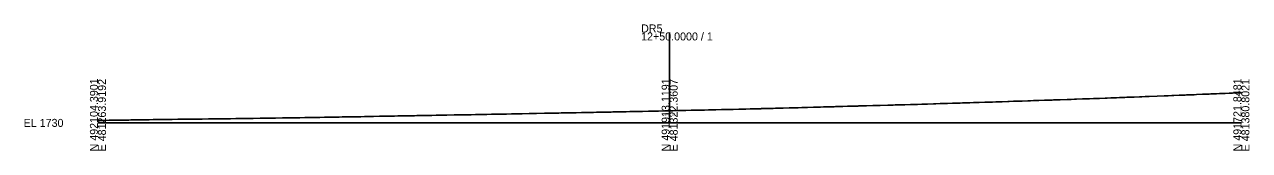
# Model space of a CAD drawing. Extents: x -26 to 403, y -10 to 2534.
# Drawn here: x -25.7 to 402.8, y 2490.3 to 2534.5 of the extents above; entities that cross this region are included whole.
import ezdxf

# ---------------------------------------------------------------- set-up
doc = ezdxf.new("R2010")
doc.units = 0
for name, color, linetype in [('Exist Cross Section Cell', 7, 'Continuous'), ('Exist XS Center Line Elevation Label', 7, 'Continuous'), ('Exist XS Ground Line', 7, 'Continuous'), ('Scratch_Level_5', 7, 'Continuous')]:
    doc.layers.add(name, color=color, linetype=linetype)

msp = doc.modelspace()

# ---------------------------------------------------------------- linework, layer by layer
at = {"layer": 'Exist Cross Section Cell'}
for p, q in [((200, 2500), (200, 2531.7)), ((0, 2500), (200, 2500)), ((200, 2500), (400, 2500))]:
    msp.add_line(p, q, dxfattribs=at)
at = {"layer": 'Exist XS Ground Line'}
msp.add_lwpolyline([(0, 2500.85), (0.97, 2500.87), (1.82, 2500.88), (2.29, 2500.88), (3.87, 2500.91), (4.94, 2500.93), (6.19, 2500.95), (7.26, 2500.96), (8.12, 2500.98), (9.65, 2501), (10.78, 2501.01), (11.56, 2501.03), (12.28, 2501.04), (13.59, 2501.05), (14.87, 2501.07), (15.84, 2501.09), (17.48, 2501.11), (17.92, 2501.12), (19.34, 2501.14), (20.08, 2501.15), (20.42, 2501.15), (22.53, 2501.18), (24.23, 2501.21), (25.34, 2501.22), (25.94, 2501.23), (27.95, 2501.26), (30.28, 2501.29), (31.04, 2501.29), (31.72, 2501.3), (33.18, 2501.32), (35.47, 2501.35), (35.94, 2501.35), (36.48, 2501.36), (38.69, 2501.39), (40.44, 2501.41), (41.01, 2501.42), (41.95, 2501.43), (43.64, 2501.44), (45.01, 2501.46), (46.35, 2501.47), (48.24, 2501.5), (48.86, 2501.51), (50.54, 2501.52), (51.47, 2501.54), (53.64, 2501.57), (54.26, 2501.58), (56.71, 2501.62), (57.94, 2501.64), (59.31, 2501.65), (59.98, 2501.66), (62.17, 2501.7), (64.54, 2501.74), (65.97, 2501.76), (67.16, 2501.78), (68, 2501.79), (69.78, 2501.81), (70.68, 2501.83), (72.38, 2501.86), (74, 2501.89), (75.02, 2501.9), (76.89, 2501.93), (77.6, 2501.94), (79.25, 2501.97), (80.22, 2501.98), (80.64, 2501.99), (82.85, 2502.02), (84.43, 2502.05), (85.45, 2502.07), (86, 2502.08), (88.09, 2502.11), (90.01, 2502.15), (90.68, 2502.16), (92, 2502.18), (93.3, 2502.21), (94.03, 2502.22), (95.92, 2502.26), (96.38, 2502.26), (98.52, 2502.3), (100.03, 2502.33), (101.15, 2502.35), (103.23, 2502.39), (103.74, 2502.4), (104.91, 2502.42), (106.02, 2502.44), (106.36, 2502.45), (106.99, 2502.46), (108.99, 2502.49), (110.78, 2502.53), (111.59, 2502.54), (113.47, 2502.57), (114.21, 2502.59), (114.53, 2502.59), (116.83, 2502.63), (118.29, 2502.66), (119.43, 2502.68), (120.06, 2502.69), (122.08, 2502.72), (124.66, 2502.77), (126.04, 2502.79), (127.29, 2502.82), (128.07, 2502.83), (129.91, 2502.86), (130.57, 2502.87), (132.04, 2502.9), (132.5, 2502.91), (134.06, 2502.93), (135.14, 2502.95), (136.08, 2502.97), (137.73, 2503), (139.09, 2503.02), (140.35, 2503.04), (142.08, 2503.08), (142.97, 2503.09), (144.65, 2503.13), (145.58, 2503.14), (147.68, 2503.18), (148.41, 2503.2), (150.82, 2503.25), (152.18, 2503.27), (153.42, 2503.29), (156.25, 2503.35), (158.66, 2503.4), (159.73, 2503.42), (161.26, 2503.45), (162.07, 2503.47), (164.1, 2503.5), (164.82, 2503.52), (166.51, 2503.55), (167.26, 2503.57), (169.1, 2503.6), (170.08, 2503.62), (171.72, 2503.65), (172.1, 2503.66), (173.37, 2503.69), (174.35, 2503.7), (174.78, 2503.71), (176.95, 2503.75), (178.09, 2503.78), (179.56, 2503.8), (180.11, 2503.82), (182.31, 2503.86), (184.8, 2503.91), (186.08, 2503.94), (187.4, 2503.96), (188.12, 2503.98), (190.13, 2504.02), (190.48, 2504.03), (192.64, 2504.07), (193.59, 2504.09), (195.25, 2504.13), (196.11, 2504.15), (198.14, 2504.2), (199.05, 2504.22), (200.15, 2504.24), (200.48, 2504.25), (201.1, 2504.26), (203.09, 2504.3), (204.88, 2504.35), (205.7, 2504.37), (207.56, 2504.41), (208.31, 2504.43), (210.15, 2504.46), (210.94, 2504.48), (212.17, 2504.51), (213.55, 2504.54), (216.14, 2504.6), (218.15, 2504.64), (218.77, 2504.66), (220.16, 2504.69), (221.4, 2504.72), (222.17, 2504.74), (224.18, 2504.79), (224.69, 2504.8), (226.62, 2504.85), (228.16, 2504.89), (229.23, 2504.91), (230.17, 2504.94), (231.85, 2504.98), (232.17, 2504.99), (233.25, 2505.01), (234.46, 2505.04), (236.19, 2505.09), (237.08, 2505.11), (238.76, 2505.15), (239.68, 2505.18), (241.78, 2505.24), (242.29, 2505.25), (244.18, 2505.3), (244.91, 2505.32), (246.19, 2505.36), (247.54, 2505.4), (248.2, 2505.41), (250.35, 2505.47), (252.76, 2505.54), (253.82, 2505.57), (255.38, 2505.61), (257.58, 2505.68), (257.98, 2505.69), (258.88, 2505.72), (260.2, 2505.75), (260.59, 2505.77), (262.21, 2505.81), (263.22, 2505.84), (264.22, 2505.87), (265.84, 2505.91), (266.22, 2505.92), (267.47, 2505.96), (268.45, 2505.98), (268.88, 2506), (271.06, 2506.06), (272.64, 2506.1), (273.67, 2506.13), (276.28, 2506.21), (278.22, 2506.26), (278.9, 2506.28), (280.23, 2506.32), (281.51, 2506.35), (282.23, 2506.37), (284.24, 2506.43), (284.6, 2506.44), (286.24, 2506.49), (286.75, 2506.5), (288.24, 2506.55), (289.36, 2506.58), (290.25, 2506.61), (292.25, 2506.66), (293.13, 2506.69), (294.59, 2506.74), (295.24, 2506.76), (297.2, 2506.82), (298.99, 2506.87), (299.81, 2506.9), (301.67, 2506.96), (302.42, 2506.98), (304.25, 2507.04), (305.04, 2507.06), (306.26, 2507.1), (307.66, 2507.14), (308.26, 2507.16), (310.27, 2507.22), (312.27, 2507.29), (312.89, 2507.31), (314.06, 2507.35), (315.5, 2507.4), (316.27, 2507.43), (318.27, 2507.49), (318.77, 2507.51), (320.28, 2507.56), (320.73, 2507.57), (321.58, 2507.6), (323.34, 2507.66), (325.35, 2507.72), (325.95, 2507.75), (326.27, 2507.76), (327.33, 2507.79), (328.58, 2507.83), (329.12, 2507.85), (331.18, 2507.92), (332.87, 2507.98), (333.8, 2508.02), (334.29, 2508.03), (335.89, 2508.09), (336.65, 2508.11), (339.03, 2508.2), (340.41, 2508.24), (341.64, 2508.28), (342.3, 2508.3), (344.45, 2508.38), (346.3, 2508.45), (346.87, 2508.47), (348.3, 2508.52), (349.48, 2508.57), (350.31, 2508.6), (352.31, 2508.68), (353.01, 2508.7), (354.31, 2508.75), (354.7, 2508.77), (356.32, 2508.83), (357.33, 2508.87), (359.23, 2508.94), (359.93, 2508.97), (361.52, 2509.03), (362.55, 2509.06), (364.32, 2509.13), (365.17, 2509.17), (366.32, 2509.21), (367.77, 2509.27), (370.5, 2509.38), (373.01, 2509.47), (374.33, 2509.52), (375.63, 2509.58), (376.34, 2509.6), (378.24, 2509.68), (378.68, 2509.7), (380.34, 2509.77), (380.85, 2509.79), (381.82, 2509.83), (383.46, 2509.89), (384.33, 2509.93), (386.34, 2510.01), (387.23, 2510.05), (388.35, 2510.1), (388.69, 2510.11), (389.33, 2510.14), (391.32, 2510.22), (392.35, 2510.26), (393.92, 2510.32), (394.36, 2510.33), (395.76, 2510.39), (396.53, 2510.42), (396.87, 2510.44), (399.13, 2510.53), (400, 2510.57)], dxfattribs=at)
at = {"layer": 'Scratch_Level_5'}
msp.add_lwpolyline([(0, 2500.85), (0.97, 2500.87), (1.82, 2500.88), (2.29, 2500.88), (3.87, 2500.91), (4.94, 2500.93), (6.19, 2500.95), (7.26, 2500.96), (8.12, 2500.98), (9.65, 2501), (10.78, 2501.01), (11.56, 2501.03), (12.28, 2501.04), (13.59, 2501.05), (14.87, 2501.07), (15.84, 2501.09), (17.48, 2501.11), (17.92, 2501.12), (19.34, 2501.14), (20.08, 2501.15), (20.42, 2501.15), (22.53, 2501.18), (24.23, 2501.21), (25.34, 2501.22), (25.94, 2501.23), (27.95, 2501.26), (30.28, 2501.29), (31.04, 2501.29), (31.72, 2501.3), (33.18, 2501.32), (35.47, 2501.35), (35.94, 2501.35), (36.48, 2501.36), (38.69, 2501.39), (40.44, 2501.41), (41.01, 2501.42), (41.95, 2501.43), (43.64, 2501.44), (45.01, 2501.46), (46.35, 2501.47), (48.24, 2501.5), (48.86, 2501.51), (50.54, 2501.52), (51.47, 2501.54), (53.64, 2501.57), (54.26, 2501.58), (56.71, 2501.62), (57.94, 2501.64), (59.31, 2501.65), (59.98, 2501.66), (62.17, 2501.7), (64.54, 2501.74), (65.97, 2501.76), (67.16, 2501.78), (68, 2501.79), (69.78, 2501.81), (70.68, 2501.83), (72.38, 2501.86), (74, 2501.89), (75.02, 2501.9), (76.89, 2501.93), (77.6, 2501.94), (79.25, 2501.97), (80.22, 2501.98), (80.64, 2501.99), (82.85, 2502.02), (84.43, 2502.05), (85.45, 2502.07), (86, 2502.08), (88.09, 2502.11), (90.01, 2502.15), (90.68, 2502.16), (92, 2502.18), (93.3, 2502.21), (94.03, 2502.22), (95.92, 2502.26), (96.38, 2502.26), (98.52, 2502.3), (100.03, 2502.33), (101.15, 2502.35), (103.23, 2502.39), (103.74, 2502.4), (104.91, 2502.42), (106.02, 2502.44), (106.36, 2502.45), (106.99, 2502.46), (108.99, 2502.49), (110.78, 2502.53), (111.59, 2502.54), (113.47, 2502.57), (114.21, 2502.59), (114.53, 2502.59), (116.83, 2502.63), (118.29, 2502.66), (119.43, 2502.68), (120.06, 2502.69), (122.08, 2502.72), (124.66, 2502.77), (126.04, 2502.79), (127.29, 2502.82), (128.07, 2502.83), (129.91, 2502.86), (130.57, 2502.87), (132.04, 2502.9), (132.5, 2502.91), (134.06, 2502.93), (135.14, 2502.95), (136.08, 2502.97), (137.73, 2503), (139.09, 2503.02), (140.35, 2503.04), (142.08, 2503.08), (142.97, 2503.09), (144.65, 2503.13), (145.58, 2503.14), (147.68, 2503.18), (148.41, 2503.2), (150.82, 2503.25), (152.18, 2503.27), (153.42, 2503.29), (156.25, 2503.35), (158.66, 2503.4), (159.73, 2503.42), (161.26, 2503.45), (162.07, 2503.47), (164.1, 2503.5), (164.82, 2503.52), (166.51, 2503.55), (167.26, 2503.57), (169.1, 2503.6), (170.08, 2503.62), (171.72, 2503.65), (172.1, 2503.66), (173.37, 2503.69), (174.35, 2503.7), (174.78, 2503.71), (176.95, 2503.75), (178.09, 2503.78), (179.56, 2503.8), (180.11, 2503.82), (182.31, 2503.86), (184.8, 2503.91), (186.08, 2503.94), (187.4, 2503.96), (188.12, 2503.98), (190.13, 2504.02), (190.48, 2504.03), (192.64, 2504.07), (193.59, 2504.09), (195.25, 2504.13), (196.11, 2504.15), (198.14, 2504.2), (199.05, 2504.22), (200.15, 2504.24), (200.48, 2504.25), (201.1, 2504.26), (203.09, 2504.3), (204.88, 2504.35), (205.7, 2504.37), (207.56, 2504.41), (208.31, 2504.43), (210.15, 2504.46), (210.94, 2504.48), (212.17, 2504.51), (213.55, 2504.54), (216.14, 2504.6), (218.15, 2504.64), (218.77, 2504.66), (220.16, 2504.69), (221.4, 2504.72), (222.17, 2504.74), (224.18, 2504.79), (224.69, 2504.8), (226.62, 2504.85), (228.16, 2504.89), (229.23, 2504.91), (230.17, 2504.94), (231.85, 2504.98), (232.17, 2504.99), (233.25, 2505.01), (234.46, 2505.04), (236.19, 2505.09), (237.08, 2505.11), (238.76, 2505.15), (239.68, 2505.18), (241.78, 2505.24), (242.29, 2505.25), (244.18, 2505.3), (244.91, 2505.32), (246.19, 2505.36), (247.54, 2505.4), (248.2, 2505.41), (250.35, 2505.47), (252.76, 2505.54), (253.82, 2505.57), (255.38, 2505.61), (257.58, 2505.68), (257.98, 2505.69), (258.88, 2505.72), (260.2, 2505.75), (260.59, 2505.77), (262.21, 2505.81), (263.22, 2505.84), (264.22, 2505.87), (265.84, 2505.91), (266.22, 2505.92), (267.47, 2505.96), (268.45, 2505.98), (268.88, 2506), (271.06, 2506.06), (272.64, 2506.1), (273.67, 2506.13), (276.28, 2506.21), (278.22, 2506.26), (278.9, 2506.28), (280.23, 2506.32), (281.51, 2506.35), (282.23, 2506.37), (284.24, 2506.43), (284.6, 2506.44), (286.24, 2506.49), (286.75, 2506.5), (288.24, 2506.55), (289.36, 2506.58), (290.25, 2506.61), (292.25, 2506.66), (293.13, 2506.69), (294.59, 2506.74), (295.24, 2506.76), (297.2, 2506.82), (298.99, 2506.87), (299.81, 2506.9), (301.67, 2506.96), (302.42, 2506.98), (304.25, 2507.04), (305.04, 2507.06), (306.26, 2507.1), (307.66, 2507.14), (308.26, 2507.16), (310.27, 2507.22), (312.27, 2507.29), (312.89, 2507.31), (314.06, 2507.35), (315.5, 2507.4), (316.27, 2507.43), (318.27, 2507.49), (318.77, 2507.51), (320.28, 2507.56), (320.73, 2507.57), (321.58, 2507.6), (323.34, 2507.66), (325.35, 2507.72), (325.95, 2507.75), (326.27, 2507.76), (327.33, 2507.79), (328.58, 2507.83), (329.12, 2507.85), (331.18, 2507.92), (332.87, 2507.98), (333.8, 2508.02), (334.29, 2508.03), (335.89, 2508.09), (336.65, 2508.11), (339.03, 2508.2), (340.41, 2508.24), (341.64, 2508.28), (342.3, 2508.3), (344.45, 2508.38), (346.3, 2508.45), (346.87, 2508.47), (348.3, 2508.52), (349.48, 2508.57), (350.31, 2508.6), (352.31, 2508.68), (353.01, 2508.7), (354.31, 2508.75), (354.7, 2508.77), (356.32, 2508.83), (357.33, 2508.87), (359.23, 2508.94), (359.93, 2508.97), (361.52, 2509.03), (362.55, 2509.06), (364.32, 2509.13), (365.17, 2509.17), (366.32, 2509.21), (367.77, 2509.27), (370.5, 2509.38), (373.01, 2509.47), (374.33, 2509.52), (375.63, 2509.58), (376.34, 2509.6), (378.24, 2509.68), (378.68, 2509.7), (380.34, 2509.77), (380.85, 2509.79), (381.82, 2509.83), (383.46, 2509.89), (384.33, 2509.93), (386.34, 2510.01), (387.23, 2510.05), (388.35, 2510.1), (388.69, 2510.11), (389.33, 2510.14), (391.32, 2510.22), (392.35, 2510.26), (393.92, 2510.32), (394.36, 2510.33), (395.76, 2510.39), (396.53, 2510.42), (396.87, 2510.44), (399.13, 2510.53), (400, 2510.57)], dxfattribs=at)

# ---------------------------------------------------------------- texts
at = {"layer": 'Exist Cross Section Cell'}
for s, p in [('DR5', (190, 2531.7)), ('12+50.0000 / 1', (190, 2528.9)), ('EL 1730', (-26, 2498.6))]:
    msp.add_text(s, height=2.8, dxfattribs=at).set_placement(p)
for s, p in [('N 492104.3901', (0, 2490)), ('E 481263.9192', (2.8, 2490)), ('N 491913.1191', (200, 2490)), ('E 481322.3607', (202.8, 2490)), ('N 491721.8481', (400, 2490)), ('E 481380.8021', (402.8, 2490))]:
    msp.add_text(s, height=2.8, rotation=90, dxfattribs=at).set_placement(p)
at = {"layer": 'Exist XS Center Line Elevation Label'}
msp.add_text('1734.24', height=0.75, dxfattribs=at).set_placement((198.23, 2502.66))

doc.saveas('drawing.dxf')
